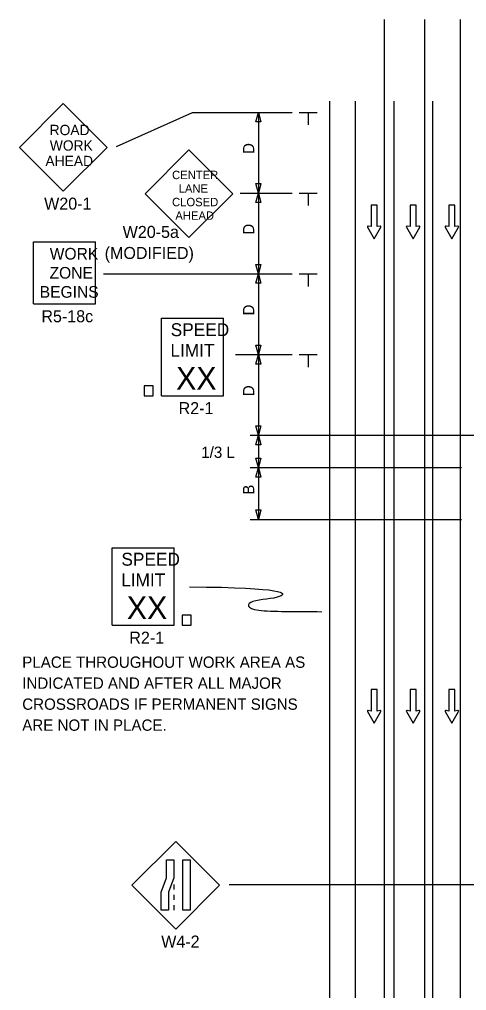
# Model space of a CAD drawing. Extents: x 16731 to 18475, y 7003 to 8262.
# Drawn here: x 16737 to 17014, y 7661 to 8262 of the extents above; entities that cross this region are included whole.
import ezdxf

# ---------------------------------------------------------------- set-up
doc = ezdxf.new("R2010")
doc.units = 0
for name, color, linetype in [('ALI_LEGAL_EX', 7, 'Continuous'), ('MT_SCRATCH_LEVEL_E', 7, 'Continuous'), ('PAVT_EDGE_EX', 7, 'Continuous'), ('TRAFFIC_SIGNS_PR', 7, 'Continuous'), ('TYPICAL_TEXT_DIMEN_PR', 7, 'Continuous')]:
    doc.layers.add(name, color=color, linetype=linetype)

msp = doc.modelspace()

# ---------------------------------------------------------------- linework, layer by layer
at = {"layer": 'ALI_LEGAL_EX'}
for p, q in [((16969.24, 7388.68), (16969.24, 8211.76)), ((16993.24, 7388.68), (16993.24, 8211.76))]:
    msp.add_line(p, q, dxfattribs=at)
for points in [[(16969.24, 8088.68), (16969.24, 8113.68)], [(16993.24, 8088.68), (16993.24, 8113.68)], [(16969.24, 7988.68), (16969.24, 8013.68)], [(16993.24, 7988.68), (16993.24, 8013.68)], [(16969.24, 7888.68), (16969.24, 7913.68)], [(16993.24, 7888.68), (16993.24, 7913.68)], [(16969.24, 7788.68), (16969.24, 7813.68)], [(16993.24, 7788.68), (16993.24, 7813.68)], [(16969.24, 7688.68), (16969.24, 7713.68)], [(16993.24, 7688.68), (16993.24, 7713.68)]]:
    msp.add_lwpolyline(points, dxfattribs=at)
at = {"layer": 'MT_SCRATCH_LEVEL_E'}
for p, q in [((16958.84, 8147.27), (16955.1, 8147.27)), ((16955.1, 8147.27), (16955.1, 8134.01)), ((16958.84, 8147.27), (16955.1, 8147.27)), ((16955.1, 8147.27), (16955.1, 8134.01)), ((16958.84, 8134.01), (16958.84, 8147.27)), ((16958.84, 8134.01), (16958.84, 8147.27)), ((16982.91, 8147.27), (16979.17, 8147.27)), ((16979.17, 8147.27), (16979.17, 8134.01)), ((16982.91, 8147.27), (16979.17, 8147.27)), ((16979.17, 8147.27), (16979.17, 8134.01)), ((16982.91, 8134.01), (16982.91, 8147.27)), ((16982.91, 8134.01), (16982.91, 8147.27)), ((17006.98, 8147.27), (17003.24, 8147.27)), ((17003.24, 8147.27), (17003.24, 8134.01)), ((17006.98, 8147.27), (17003.24, 8147.27)), ((17003.24, 8147.27), (17003.24, 8134.01)), ((17006.98, 8134.01), (17006.98, 8147.27)), ((17006.98, 8134.01), (17006.98, 8147.27)), ((16952.84, 8133.64), (16956.99, 8126.4)), ((16952.84, 8133.64), (16956.99, 8126.4)), ((16955.1, 8134.01), (16953.32, 8134.32)), ((16955.1, 8134.01), (16953.32, 8134.32)), ((16956.99, 8126.4), (16961.1, 8133.64)), ((16956.99, 8126.4), (16961.1, 8133.64)), ((16960.61, 8134.32), (16958.84, 8134.01)), ((16960.61, 8134.32), (16958.84, 8134.01)), ((16976.91, 8133.64), (16981.06, 8126.4)), ((16976.91, 8133.64), (16981.06, 8126.4)), ((16979.17, 8134.01), (16977.39, 8134.32)), ((16979.17, 8134.01), (16977.39, 8134.32)), ((16981.06, 8126.4), (16985.17, 8133.64)), ((16981.06, 8126.4), (16985.17, 8133.64)), ((16984.69, 8134.32), (16982.91, 8134.01)), ((16984.69, 8134.32), (16982.91, 8134.01)), ((17000.98, 8133.64), (17005.13, 8126.4)), ((17000.98, 8133.64), (17005.13, 8126.4)), ((17003.24, 8134.01), (17001.46, 8134.32)), ((17003.24, 8134.01), (17001.46, 8134.32)), ((17005.13, 8126.4), (17009.24, 8133.64)), ((17005.13, 8126.4), (17009.24, 8133.64)), ((17008.76, 8134.32), (17006.98, 8134.01)), ((17008.76, 8134.32), (17006.98, 8134.01)), ((16958.84, 7847.35), (16955.1, 7847.35)), ((16955.1, 7847.35), (16955.1, 7834.09)), ((16958.84, 7847.35), (16955.1, 7847.35)), ((16955.1, 7847.35), (16955.1, 7834.09)), ((16958.84, 7834.09), (16958.84, 7847.35)), ((16958.84, 7834.09), (16958.84, 7847.35)), ((16982.91, 7847.35), (16979.17, 7847.35)), ((16979.17, 7847.35), (16979.17, 7834.09)), ((16982.91, 7847.35), (16979.17, 7847.35)), ((16979.17, 7847.35), (16979.17, 7834.09)), ((16982.91, 7834.09), (16982.91, 7847.35)), ((16982.91, 7834.09), (16982.91, 7847.35)), ((17006.98, 7847.35), (17003.24, 7847.35)), ((17003.24, 7847.35), (17003.24, 7834.09)), ((17006.98, 7847.35), (17003.24, 7847.35)), ((17003.24, 7847.35), (17003.24, 7834.09)), ((17006.98, 7834.09), (17006.98, 7847.35)), ((17006.98, 7834.09), (17006.98, 7847.35)), ((16952.84, 7833.72), (16956.99, 7826.48)), ((16952.84, 7833.72), (16956.99, 7826.48)), ((16955.1, 7834.09), (16953.32, 7834.41)), ((16955.1, 7834.09), (16953.32, 7834.41)), ((16956.99, 7826.48), (16961.1, 7833.72)), ((16956.99, 7826.48), (16961.1, 7833.72)), ((16960.61, 7834.41), (16958.84, 7834.09)), ((16960.61, 7834.41), (16958.84, 7834.09)), ((16976.91, 7833.72), (16981.06, 7826.48)), ((16976.91, 7833.72), (16981.06, 7826.48)), ((16979.17, 7834.09), (16977.39, 7834.41)), ((16979.17, 7834.09), (16977.39, 7834.41)), ((16981.06, 7826.48), (16985.17, 7833.72)), ((16981.06, 7826.48), (16985.17, 7833.72)), ((16984.69, 7834.41), (16982.91, 7834.09)), ((16984.69, 7834.41), (16982.91, 7834.09)), ((17000.98, 7833.72), (17005.13, 7826.48)), ((17000.98, 7833.72), (17005.13, 7826.48)), ((17003.24, 7834.09), (17001.46, 7834.41)), ((17003.24, 7834.09), (17001.46, 7834.41)), ((17005.13, 7826.48), (17009.24, 7833.72)), ((17005.13, 7826.48), (17009.24, 7833.72)), ((17008.76, 7834.41), (17006.98, 7834.09)), ((17008.76, 7834.41), (17006.98, 7834.09))]:
    msp.add_line(p, q, dxfattribs=at)
for centre, start, end in [((16953.25, 8133.86), 80.03619, 209.77312), ((16953.25, 8133.86), 80.03619, 209.77312), ((16960.69, 8133.86), 330.42484, 99.96381), ((16960.69, 8133.86), 330.42484, 99.96381), ((16977.32, 8133.86), 80.03619, 209.77312), ((16977.32, 8133.86), 80.03619, 209.77312), ((16984.76, 8133.86), 330.42484, 99.96381), ((16984.76, 8133.86), 330.42484, 99.96381), ((17001.39, 8133.86), 80.03619, 209.77312), ((17001.39, 8133.86), 80.03619, 209.77312), ((17008.83, 8133.86), 330.42484, 99.96381), ((17008.83, 8133.86), 330.42484, 99.96381), ((16953.25, 7833.95), 80.03619, 209.77312), ((16953.25, 7833.95), 80.03619, 209.77312), ((16960.69, 7833.95), 330.42484, 99.96381), ((16960.69, 7833.95), 330.42484, 99.96381), ((16977.32, 7833.95), 80.03619, 209.77312), ((16977.32, 7833.95), 80.03619, 209.77312), ((16984.76, 7833.95), 330.42484, 99.96381), ((16984.76, 7833.95), 330.42484, 99.96381), ((17001.39, 7833.95), 80.03619, 209.77312), ((17001.39, 7833.95), 80.03619, 209.77312), ((17008.83, 7833.95), 330.42484, 99.96381), ((17008.83, 7833.95), 330.42484, 99.96381)]:
    msp.add_arc(centre, 0.463, start, end, dxfattribs=at)
at = {"layer": 'PAVT_EDGE_EX'}
for p, q in [((16963.15, 8262.34), (16963.15, 7433.15)), ((16988.15, 8262.34), (16988.15, 7433.15)), ((17010.15, 8262.34), (17010.15, 7433.15)), ((16929.24, 8211.76), (16929.24, 7413.89)), ((16945.24, 8211.76), (16945.24, 7413.89))]:
    msp.add_line(p, q, dxfattribs=at)
at = {"layer": 'TRAFFIC_SIGNS_PR'}
for p, q in [((16764.41, 8210.29), (16737.25, 8183.13)), ((16791.56, 8183.13), (16764.41, 8210.29)), ((16737.25, 8183.13), (16764.41, 8155.98)), ((16764.41, 8155.98), (16791.56, 8183.13)), ((16842.21, 8181.59), (16815.06, 8154.43)), ((16869.37, 8154.43), (16842.21, 8181.59)), ((16815.06, 8154.43), (16842.21, 8127.28)), ((16842.21, 8127.28), (16869.37, 8154.43)), ((16746.03, 8086.26), (16746.03, 8124.66)), ((16746.03, 8124.66), (16784.43, 8124.66)), ((16784.43, 8086.26), (16784.43, 8124.66)), ((16746.03, 8086.26), (16784.43, 8086.26)), ((16825.16, 8077.35), (16863.56, 8077.35)), ((16825.16, 8029.35), (16825.16, 8077.35)), ((16863.56, 8029.35), (16863.56, 8077.35)), ((16825.16, 8029.35), (16863.56, 8029.35)), ((16794.65, 7935.21), (16833.05, 7935.21)), ((16794.65, 7887.21), (16794.65, 7935.21)), ((16833.05, 7887.21), (16833.05, 7935.21)), ((16794.65, 7887.21), (16833.05, 7887.21)), ((16834.11, 7753.36), (16806.96, 7726.2)), ((16861.26, 7726.2), (16834.11, 7753.36)), ((16806.96, 7726.2), (16834.11, 7699.05)), ((16832.86, 7726.69), (16832.86, 7723.49)), ((16834.11, 7699.05), (16861.26, 7726.2)), ((16832.86, 7720.29), (16832.86, 7717.09)), ((16832.86, 7713.89), (16832.86, 7710.69))]:
    msp.add_line(p, q, dxfattribs=at)
for points in [[(16814.55, 8029.35), (16820.15, 8029.35), (16820.15, 8035.52), (16814.55, 8035.52)], [(16838.06, 7887.21), (16843.66, 7887.21), (16843.66, 7893.38), (16838.06, 7893.38)], [(16832.86, 7741.94), (16832.86, 7730.76), (16829.52, 7721.88), (16829.52, 7710.69), (16825.02, 7710.69), (16825.02, 7721.88), (16828.37, 7730.76), (16828.37, 7741.94)], [(16843, 7741.94), (16843, 7710.69), (16838.5, 7710.69), (16838.5, 7741.94)]]:
    msp.add_lwpolyline(points, close=True, dxfattribs=at)
at = {"layer": 'TYPICAL_TEXT_DIMEN_PR'}
for p, q in [((16797.29, 8183.55), (16844.35, 8204.8)), ((16844.35, 8204.8), (16906.24, 8204.8)), ((16883.67, 8198.94), (16885.24, 8204.8)), ((16885.24, 8204.8), (16885.24, 8154.8)), ((16885.24, 8204.8), (16886.81, 8198.94)), ((16910.49, 8204.8), (16921.74, 8204.8)), ((16916.11, 8204.8), (16916.11, 8197.02)), ((16885.24, 8198.94), (16883.67, 8198.94)), ((16886.81, 8198.94), (16885.24, 8198.94)), ((16885.24, 8154.8), (16883.67, 8160.66)), ((16883.67, 8160.66), (16885.24, 8160.66)), ((16885.24, 8160.66), (16886.81, 8160.66)), ((16886.81, 8160.66), (16885.24, 8154.8)), ((16874.04, 8154.8), (16906.24, 8154.8)), ((16883.67, 8148.94), (16885.24, 8154.8)), ((16885.24, 8154.8), (16885.24, 8104.8)), ((16885.24, 8154.8), (16886.81, 8148.94)), ((16910.49, 8154.8), (16921.74, 8154.8)), ((16916.11, 8154.8), (16916.11, 8147.02)), ((16885.24, 8148.94), (16883.67, 8148.94)), ((16886.81, 8148.94), (16885.24, 8148.94)), ((16885.24, 8104.8), (16883.67, 8110.66)), ((16883.67, 8110.66), (16885.24, 8110.66)), ((16885.24, 8110.66), (16886.81, 8110.66)), ((16886.81, 8110.66), (16885.24, 8104.8)), ((16789.36, 8104.8), (16906.24, 8104.8)), ((16883.67, 8098.94), (16885.24, 8104.8)), ((16885.24, 8104.8), (16885.24, 8054.8)), ((16885.24, 8104.8), (16886.81, 8098.94)), ((16910.49, 8104.8), (16921.74, 8104.8)), ((16916.11, 8104.8), (16916.11, 8097.02)), ((16885.24, 8098.94), (16883.67, 8098.94)), ((16886.81, 8098.94), (16885.24, 8098.94)), ((16885.24, 8054.8), (16883.67, 8060.66)), ((16883.67, 8060.66), (16885.24, 8060.66)), ((16885.24, 8060.66), (16886.81, 8060.66)), ((16886.81, 8060.66), (16885.24, 8054.8)), ((16871.16, 8054.8), (16906.24, 8054.8)), ((16883.67, 8048.94), (16885.24, 8054.8)), ((16885.24, 8054.8), (16885.24, 8004.8)), ((16885.24, 8054.8), (16886.81, 8048.94)), ((16910.49, 8054.8), (16921.74, 8054.8)), ((16916.11, 8054.8), (16916.11, 8047.02)), ((16885.24, 8048.94), (16883.67, 8048.94)), ((16886.81, 8048.94), (16885.24, 8048.94)), ((16885.24, 8004.8), (16883.67, 8010.66)), ((16883.67, 8010.66), (16885.24, 8010.66)), ((16885.24, 8010.66), (16886.81, 8010.66)), ((16886.81, 8010.66), (16885.24, 8004.8)), ((16880.24, 8004.8), (17031.69, 8004.8)), ((16883.67, 7998.94), (16885.24, 8004.8)), ((16885.24, 8004.8), (16885.24, 7984.81)), ((16885.24, 8004.8), (16886.81, 7998.94)), ((16885.24, 7998.94), (16883.67, 7998.94)), ((16886.81, 7998.94), (16885.24, 7998.94)), ((16885.24, 7984.81), (16883.67, 7990.67)), ((16883.67, 7990.67), (16885.24, 7990.67)), ((16885.24, 7990.67), (16886.81, 7990.67)), ((16886.81, 7990.67), (16885.24, 7984.81)), ((16880.24, 7984.81), (17011.11, 7984.81)), ((16883.67, 7978.95), (16885.24, 7984.81)), ((16885.24, 7984.81), (16885.24, 7952.75)), ((16885.24, 7984.81), (16886.81, 7978.95)), ((16885.24, 7978.95), (16883.67, 7978.95)), ((16886.81, 7978.95), (16885.24, 7978.95)), ((16885.24, 7952.75), (16883.67, 7958.61)), ((16883.67, 7958.61), (16885.24, 7958.61)), ((16885.24, 7958.61), (16886.81, 7958.61)), ((16886.81, 7958.61), (16885.24, 7952.75)), ((16880.24, 7952.75), (17011.11, 7952.75)), ((17042.95, 7726.39), (16867.24, 7726.39))]:
    msp.add_line(p, q, dxfattribs=at)
msp.add_open_spline([(16842.59, 7910.95), (16902.83, 7910.59), (16902.83, 7903.32), (16877.65, 7903.32), (16877.65, 7894.79), (16909.02, 7895.99), (16924.52, 7895.57)], degree=3, dxfattribs=at)

# ---------------------------------------------------------------- texts
at = {"layer": 'TRAFFIC_SIGNS_PR'}
for s, height, p in [('ROAD', 6.4, (16755.95, 8190.67)), ('WORK', 6.4, (16756.06, 8181.07)), ('AHEAD', 6.4, (16753.36, 8171.47)), ('CENTER', 5.2, (16831.79, 8163.44)), ('LANE', 5.2, (16835.87, 8155.04)), ('W20-1', 7.44, (16752.57, 8144.54)), ('CLOSED', 5.2, (16831.79, 8146.64)), ('AHEAD', 5.2, (16833.82, 8138.24)), ('W20-5a', 7.44, (16801.2, 8127.04)), ('WORK', 7.217, (16756.03, 8113.63)), ('(MODIFIED)', 7.44, (16790.05, 8114)), ('ZONE', 7.217, (16755.91, 8101.82)), ('BEGINS', 7.217, (16749.84, 8090.01)), ('R5-18c', 7.44, (16750.84, 8074.82)), ('SPEED', 8, (16830.93, 8066.21)), ('LIMIT', 8, (16830.77, 8053.41)), ('XX', 14.031, (16834.28, 8033.1)), ('R2-1', 7.44, (16835.84, 8017.91)), ('SPEED', 8, (16800.41, 7924.07)), ('LIMIT', 8, (16800.25, 7911.27)), ('XX', 14.031, (16803.76, 7890.97)), ('R2-1', 7.44, (16805.32, 7875.77)), ('PLACE THROUGHOUT WORK AREA AS', 7, (16739.01, 7860.84)), ('INDICATED AND AFTER ALL MAJOR', 7, (16739.01, 7847.84)), ('CROSSROADS IF PERMANENT SIGNS', 7, (16739.01, 7834.84)), ('ARE NOT IN PLACE.', 7, (16739.01, 7821.84)), ('W4-2', 7.44, (16825.07, 7687.61))]:
    msp.add_text(s, height=height, dxfattribs=at).set_placement(p)
at = {"layer": 'TYPICAL_TEXT_DIMEN_PR'}
for s, p in [('D', (16882.68, 8179.02)), ('D', (16882.68, 8129.02)), ('D', (16882.68, 8079.02)), ('D', (16882.68, 8029.02)), ('B', (16882.68, 7968.02))]:
    msp.add_text(s, height=7, rotation=90, dxfattribs=at).set_placement(p)
msp.add_text('1/3 L', height=7, dxfattribs=at).set_placement((16849.87, 7990.81))

doc.saveas('drawing.dxf')
